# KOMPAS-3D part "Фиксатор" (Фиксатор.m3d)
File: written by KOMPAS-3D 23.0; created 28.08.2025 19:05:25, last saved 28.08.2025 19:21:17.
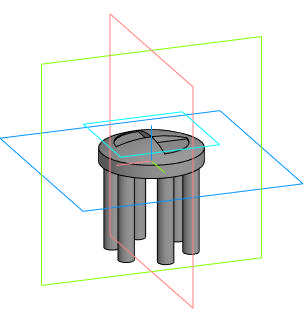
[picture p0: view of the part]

Document properties: Автор: Lost; Полное имя файла: C:\Users\Lost\Desktop\Вариант 1\Фиксатор.m3d

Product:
- Body: Тело 1
    Масса: 0.018441
- Body: Тело 2
    Масса: 0.003267
- Part/product: Фиксатор
    Масса: 0.021708

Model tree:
1. Эскиз:1  (with: Элемент вращения:2, Элемент выдавливания:2)  (labels: C:\Users\Lost\Desktop\Вариант 1\Сборка колеса.a3d)
2. Элемент выдавливания:1
     Расстояние 2 = 20
3. Эскиз:2  (with: Элемент выдавливания:1)
4. Элемент выдавливания:2
     Расстояние 1 = 3
5. Эскиз:3  (with: Элемент выдавливания:2)
6. Элемент вращения:1
     Угол 1 = 360
7. Смещенная плоскость:1  (with: Элемент выдавливания:2)
     Расстояние = 3
8. Эскиз:4
9. Элемент выдавливания:3
     Расстояние 2 = 2
10. Массив по концентрической сетке:1  (with: Элемент выдавливания:3, Смещенная плоскость:1, Элемент выдавливания:2)  (2 pattern instances)
     Шаг 2 = 360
